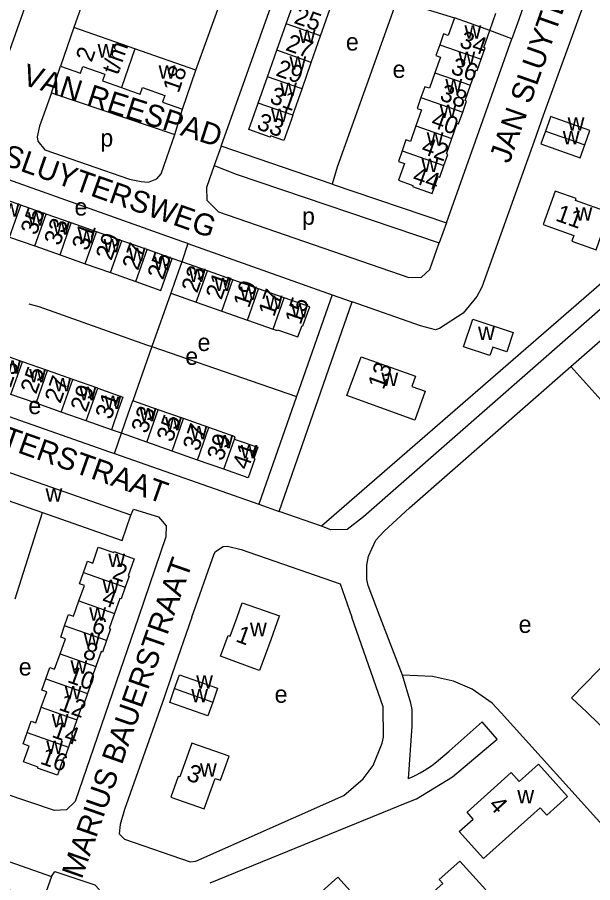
# Model space of a CAD drawing. Extents: x 162804 to 165059, y 381530 to 382901.
# Drawn here: x 163766.6 to 163898.9, y 381689 to 381888 of the extents above; entities that cross this region are included whole.
import ezdxf

# ---------------------------------------------------------------- set-up
doc = ezdxf.new("R2010")
doc.units = 0
for name, color, linetype in [('BLT_Basislijn', 7, 'Continuous'), ('BLT_Bebouwing', 7, 'Continuous'), ('BLT_Centroide', 7, 'Continuous'), ('BLT_Huisnummer', 7, 'Continuous'), ('BLT_Huisnummer_ tussenligend', 7, 'Continuous'), ('BLT_Huisnummer_reeks', 7, 'Continuous'), ('BLT_Onderverdeling_panden', 7, 'Continuous'), ('BLT_Straatnaam', 7, 'Continuous')]:
    doc.layers.add(name, color=color, linetype=linetype)

msp = doc.modelspace()

# ---------------------------------------------------------------- linework, layer by layer
at = {"layer": 'BLT_Basislijn'}
for p, q in [((163788.27, 381910.44), (163779.63, 381885.72)), ((163807.7, 381875.9), (163816.54, 381900.59)), ((163813.48, 381858.37), (163828.41, 381900.2)), ((163853.91, 381892.07), (163867.12, 381887.9)), ((163875.28, 381885.03), (163876.65, 381889)), ((163880.33, 381883.04), (163875.28, 381885.03)), ((163865.32, 381840.75), (163880.33, 381883.04)), ((163774.46, 381870.69), (163776.51, 381876.8)), ((163774.46, 381870.69), (163802.85, 381861.05)), ((163802.85, 381861.05), (163804.56, 381866.92)), ((163813.48, 381858.37), (163811.88, 381853.92)), ((163839.02, 381849.66), (163813.48, 381858.37)), ((163839.02, 381849.66), (163865.32, 381840.75)), ((163865.32, 381840.75), (163863.61, 381836.11)), ((163805.79, 381835.96), (163804.42, 381831.78)), ((163805.79, 381835.96), (163839.02, 381824.17)), ((163804.42, 381831.78), (163802.23, 381832.53)), ((163801.88, 381824.57), (163797.55, 381812.29)), ((163839.02, 381824.17), (163830.8, 381800.83)), ((163839.02, 381824.17), (163843.59, 381822.59)), ((163826.85, 381774.33), (163843.59, 381822.59)), ((163797.55, 381812.29), (163793.15, 381799.8)), ((163797.55, 381812.29), (163830.8, 381800.83)), ((163945.65, 381750), (163893.9, 381807.67)), ((163830.8, 381800.83), (163822.15, 381776.01)), ((163790.53, 381792.34), (163788.24, 381793.15)), ((163788.98, 381787.65), (163790.53, 381792.34)), ((163788.98, 381787.65), (163822.15, 381776.01)), ((163822.15, 381776.01), (163826.85, 381774.33)), ((163766.09, 381754.26), (163772.39, 381774.1)), ((163836.54, 381770.96), (163826.85, 381774.33)), ((163806.77, 381750), (163811.86, 381764.57)), ((163811.86, 381764.57), (163812.21, 381765.14)), ((163812.21, 381765.14), (163813.96, 381766.29)), ((163813.96, 381766.29), (163814.98, 381766.38)), ((163814.98, 381766.38), (163818.1, 381765.63)), ((163818.1, 381765.63), (163840.85, 381757.69)), ((163840.85, 381757.69), (163843.55, 381750)), ((163806.77, 381750), (163802.23, 381737.02)), ((163850.78, 381729.4), (163843.55, 381750)), ((163802.23, 381737.02), (163800.3, 381731.34)), ((163800.3, 381731.34), (163791.29, 381705.82)), ((163850.81, 381722.4), (163850.78, 381729.4)), ((163876.99, 381721.98), (163873.49, 381725.92)), ((163848.43, 381715.88), (163850.49, 381721.07)), ((163850.49, 381721.07), (163850.81, 381722.4)), ((163846.12, 381712.82), (163848.43, 381715.88)), ((163841.67, 381709.03), (163846.12, 381712.82)), ((163807.66, 381693.94), (163841.67, 381709.03)), ((163810.98, 381688.95), (163856.26, 381707.37)), ((163791.29, 381705.82), (163790.24, 381702.34)), ((163790.24, 381702.34), (163790.02, 381700.23)), ((163790.02, 381700.23), (163791.25, 381698.94)), ((163791.25, 381698.94), (163806.38, 381693.73)), ((163806.38, 381693.73), (163807.66, 381693.94))]:
    msp.add_line(p, q, dxfattribs=at)
for points in [[(163942.85, 382045.24), (163943.88, 382045.91), (163944.68, 382046.18), (163945.43, 382046.3), (163946.28, 382046.34), (163947.14, 382046.2), (163947.91, 382045.97), (163948.94, 382045.37), (163974.77, 382023.71), (164048.11, 381956.56), (164048.67, 381955.87), (164048.35, 381950.3), (163846.25, 381773.14), (163842.47, 381770.18), (163838.71, 381770.12), (163836.54, 381770.96)], [(163942.85, 382045.24), (163967.78, 382024.92), (164044.46, 381954.63), (164045.58, 381953.26), (163979.85, 381895.4), (163836.54, 381770.96)], [(163890.62, 381912.42), (163881.93, 381887.55), (163880.33, 381883.04)], [(163772.36, 381901.83), (163772.22, 381901.46), (163761.67, 381871.69)], [(163897.29, 381892.29), (163887.52, 381865.46), (163885.43, 381859.5), (163873.4, 381825.92), (163872.25, 381823.78), (163869.13, 381819.97), (163863.73, 381816.43), (163862.76, 381816.1), (163859.35, 381817.06), (163843.59, 381822.59)], [(163853.63, 381891.26), (163840.14, 381853.54), (163839.02, 381849.66)], [(163774.46, 381870.69), (163771.74, 381863.01), (163771.19, 381860.5), (163771.32, 381859.51), (163772.94, 381857.55), (163792.43, 381850.82), (163795.08, 381850.24), (163796.78, 381850.12), (163798.66, 381850.89), (163799.69, 381852.04), (163802.85, 381861.05)], [(163805.79, 381835.96), (163804.41, 381836.45), (163745.66, 381857.35)], [(163811.88, 381853.92), (163810.15, 381848.84), (163810.21, 381845.93), (163812.91, 381843.27), (163856.64, 381828.17), (163859.57, 381828.22), (163861.48, 381830), (163863.61, 381836.11)], [(163811.88, 381853.92), (163816.9, 381851.92), (163863.61, 381836.11)], [(163893.9, 381807.67), (163920.22, 381830.74)], [(163769.24, 381822.12), (163771.58, 381821.52), (163796.29, 381812.72), (163797.55, 381812.29)], [(163728.92, 381808.74), (163787.79, 381788.07), (163788.98, 381787.65)], [(163850.02, 381750), (163847.31, 381757.29), (163847.02, 381758.69), (163847.01, 381761.96), (163847.35, 381764.06), (163849.06, 381767.73), (163850.95, 381769.84), (163856.82, 381775.19), (163893.9, 381807.67)], [(163792.74, 381773.48), (163793.32, 381774.87), (163799.06, 381773.08), (163800.81, 381771.08), (163800.8, 381768.54), (163794.46, 381750)], [(163794.46, 381750), (163779.95, 381707.63), (163777.95, 381705.74), (163775.14, 381705.58), (163751.94, 381713.38)], [(163855.15, 381736.66), (163850.02, 381750)], [(163856.53, 381712.88), (163857.44, 381724.98), (163857.39, 381728.81), (163857.07, 381730.24), (163855.15, 381736.66)], [(163902.6, 381700.58), (163877.89, 381728.02), (163875.83, 381730.23), (163871.2, 381733.44), (163866.88, 381735.3), (163862.11, 381736.41), (163855.15, 381736.66)], [(163863.44, 381717.12), (163863.45, 381717.13), (163865.92, 381719.2), (163873.49, 381725.92)], [(163856.26, 381707.37), (163858.42, 381708.25), (163866.68, 381713.32), (163876.99, 381721.98)], [(163774.46, 381690.38), (163775.25, 381691.51), (163784.41, 381688.49), (163785.52, 381687.31)]]:
    msp.add_lwpolyline(points, dxfattribs=at)
msp.add_arc((163846.54, 381736.91), 26.02, 292.575, 310.4932, dxfattribs=at)
at = {"layer": 'BLT_Bebouwing'}
for p, q in [((163828.44, 381886.52), (163830.58, 381892.6)), ((163836.36, 381883.73), (163838.5, 381889.81)), ((163826.3, 381880.44), (163828.44, 381886.52)), ((163779.63, 381885.72), (163776.51, 381876.8)), ((163793.67, 381880.81), (163779.63, 381885.72)), ((163834.22, 381877.65), (163836.36, 381883.73)), ((163807.7, 381875.9), (163793.67, 381880.81)), ((163824.16, 381874.36), (163826.3, 381880.44)), ((163832.08, 381871.57), (163834.22, 381877.65)), ((163804.56, 381866.92), (163807.7, 381875.9)), ((163822.02, 381868.28), (163824.16, 381874.36)), ((163829.94, 381865.49), (163832.08, 381871.57)), ((163767.41, 381844.81), (163761.61, 381846.85)), ((163773.22, 381842.76), (163767.41, 381844.81)), ((163779.02, 381840.72), (163773.22, 381842.76)), ((163784.83, 381838.67), (163779.02, 381840.72)), ((163790.63, 381836.62), (163784.83, 381838.67)), ((163764.83, 381837.47), (163770.63, 381835.43)), ((163796.44, 381834.58), (163790.63, 381836.62)), ((163770.63, 381835.43), (163776.44, 381833.38)), ((163802.23, 381832.53), (163796.44, 381834.58)), ((163776.44, 381833.38), (163782.24, 381831.33)), ((163782.24, 381831.33), (163788.05, 381829.29)), ((163810.31, 381829.71), (163804.42, 381831.78)), ((163788.05, 381829.29), (163793.85, 381827.24)), ((163816.19, 381827.63), (163810.31, 381829.71)), ((163822.07, 381825.56), (163816.19, 381827.63)), ((163801.88, 381824.57), (163807.77, 381822.5)), ((163827.95, 381823.49), (163822.07, 381825.56)), ((163807.77, 381822.5), (163813.65, 381820.42)), ((163813.65, 381820.42), (163819.53, 381818.35)), ((163819.53, 381818.35), (163825.41, 381816.28)), ((163767.78, 381808.79), (163762.01, 381810.83)), ((163773.56, 381806.76), (163767.78, 381808.79)), ((163779.34, 381804.73), (163773.56, 381806.76)), ((163785.11, 381802.7), (163779.34, 381804.73)), ((163770.92, 381799.24), (163765.14, 381801.28)), ((163776.69, 381797.21), (163770.92, 381799.24)), ((163798.99, 381797.75), (163793.15, 381799.8)), ((163782.47, 381795.18), (163776.69, 381797.21)), ((163804.83, 381795.7), (163798.99, 381797.75)), ((163788.24, 381793.15), (163782.47, 381795.18)), ((163810.66, 381793.64), (163804.83, 381795.7)), ((163796.36, 381790.29), (163790.53, 381792.34)), ((163802.2, 381788.23), (163796.36, 381790.29)), ((163808.04, 381786.18), (163802.2, 381788.23)), ((163792.74, 381773.48), (163758.13, 381785.57)), ((163814.08, 381784.06), (163808.04, 381786.18)), ((163788.98, 381750.91), (163788.66, 381750)), ((163777.49, 381748.07), (163778.17, 381750)), ((163751.28, 381698.53), (163774.46, 381690.38))]:
    msp.add_line(p, q, dxfattribs=at)
for points in [[(163867.12, 381887.9), (163865.7, 381883.86), (163864.65, 381884.23), (163863.77, 381881.72)], [(163875.28, 381885.03), (163870.56, 381886.69), (163867.12, 381887.9)], [(163873.3, 381878.37), (163874.22, 381881), (163873.9, 381881.12), (163875.28, 381885.03)], [(163863.77, 381881.72), (163862.89, 381879.22), (163863.9, 381878.87), (163862.63, 381875.28)], [(163870.82, 381872.4), (163872.05, 381875.89), (163872.38, 381875.77), (163873.3, 381878.37)], [(163776.51, 381876.8), (163781.15, 381875.18), (163781.67, 381876.68), (163786.71, 381874.91), (163786.18, 381873.4), (163790.54, 381871.86)], [(163862.63, 381875.28), (163861.37, 381871.69), (163860.31, 381872.06), (163859.43, 381869.57)], [(163869.03, 381866.19), (163869.94, 381868.77), (163869.59, 381868.89), (163870.82, 381872.4)], [(163790.54, 381871.86), (163792.67, 381871.11), (163794.89, 381870.34), (163795.41, 381871.85), (163800.55, 381870.05), (163800.01, 381868.51), (163804.56, 381866.92)], [(163829.94, 381865.49), (163829.56, 381864.4), (163827.9, 381859.68), (163824.84, 381860.76), (163824.74, 381860.49), (163819.88, 381862.2), (163822.02, 381868.28)], [(163859.43, 381869.57), (163858.56, 381867.08), (163859.56, 381866.72), (163858.28, 381863.09)], [(163866.55, 381860.18), (163867.78, 381863.66), (163868.1, 381863.55), (163869.03, 381866.19)], [(163889.12, 381864.85), (163888.06, 381861.87)], [(163897.09, 381858.67), (163898.27, 381862), (163889.24, 381865.19), (163889.12, 381864.85)], [(163858.28, 381863.09), (163857, 381859.45), (163855.98, 381859.81), (163855.11, 381857.33)], [(163864.71, 381853.95), (163865.6, 381856.49), (163865.3, 381856.6), (163866.55, 381860.18)], [(163888.06, 381861.87), (163887.01, 381858.89), (163896.04, 381855.69), (163897.09, 381858.67)], [(163855.11, 381857.33), (163854.23, 381854.85), (163855.62, 381854.36), (163854.28, 381850.53), (163857.58, 381849.37), (163857.48, 381849.09), (163862.02, 381847.49), (163863.39, 381851.38), (163863.76, 381851.25), (163864.71, 381853.95)], [(163902.74, 381843.12), (163894.96, 381845.88), (163895.12, 381846.31), (163890.27, 381848.03), (163887.55, 381840.34), (163894.6, 381837.84), (163894.14, 381836.53), (163899.71, 381834.56), (163902.74, 381843.12)], [(163793.85, 381827.24), (163799.65, 381825.2), (163800.57, 381827.82), (163802.23, 381832.53)], [(163804.42, 381831.78), (163802.76, 381827.06), (163801.88, 381824.57)], [(163825.41, 381816.28), (163826.33, 381815.95), (163826.41, 381816.17), (163831.15, 381814.5), (163832.08, 381817.12), (163832.3, 381817.04), (163833.84, 381821.41), (163827.95, 381823.49)], [(163785.11, 381802.7), (163790.88, 381800.67), (163789.9, 381797.87), (163788.24, 381793.15)], [(163790.53, 381792.34), (163792.18, 381797.06), (163793.15, 381799.8)], [(163816.52, 381791.02), (163816.7, 381791.52), (163810.66, 381793.64)], [(163816.52, 381791.02), (163817.18, 381790.79), (163821.9, 381789.13), (163820.98, 381786.53), (163821.24, 381786.44), (163819.71, 381782.08), (163814.08, 381784.06)], [(163758.13, 381785.57), (163756.11, 381779.79), (163772.39, 381774.1)], [(163772.39, 381774.1), (163790.72, 381767.69), (163792.74, 381773.48)], [(163781.84, 381760.32), (163782.75, 381762.91), (163783.94, 381762.49), (163785.23, 381766.17), (163788.8, 381764.91), (163788.87, 381765.11), (163793.46, 381763.49), (163792.09, 381759.58), (163792.31, 381759.5), (163791.42, 381756.95)], [(163780.79, 381753.79), (163782.03, 381757.33), (163780.93, 381757.72), (163781.84, 381760.32)], [(163791.42, 381756.95), (163790.47, 381754.25), (163790.19, 381754.35), (163788.98, 381750.91)], [(163778.17, 381750), (163778.4, 381750.65), (163779.54, 381750.25), (163780.79, 381753.79)], [(163817.15, 381750), (163818.33, 381753.35), (163826.88, 381750.32), (163826.77, 381750)], [(163788.66, 381750), (163787.73, 381747.44), (163788.04, 381747.33), (163787.1, 381744.68)], [(163826.77, 381750), (163824.88, 381744.8), (163822.33, 381737.77), (163821.02, 381738.26), (163813.34, 381741.07), (163815.09, 381745.82), (163815.54, 381745.66), (163817.15, 381750)], [(163903.36, 381741), (163894.09, 381731.47), (163897.54, 381728.17), (163903.09, 381722.79), (163912.2, 381732.24), (163913.86, 381730.76), (163925.19, 381742.22), (163933.11, 381734.68), (163931.8, 381733.31), (163934.81, 381730.43), (163941.8, 381737.51), (163928.76, 381750)], [(163776.43, 381741.59), (163777.66, 381745.08), (163776.59, 381745.46), (163777.49, 381748.07)], [(163787.1, 381744.68), (163786.17, 381742.02), (163785.89, 381742.11), (163784.68, 381738.67)], [(163773.18, 381735.85), (163774.11, 381738.48), (163775.19, 381738.09), (163776.43, 381741.59)], [(163784.68, 381738.67), (163783.4, 381735.08), (163783.64, 381734.99), (163782.75, 381732.47)], [(163802.78, 381733.61), (163803.9, 381736.77), (163812.67, 381733.67), (163811.55, 381730.51)], [(163772.11, 381729.3), (163773.36, 381732.84), (163772.25, 381733.23), (163773.18, 381735.85)], [(163801.66, 381730.44), (163802.78, 381733.61)], [(163782.75, 381732.47), (163781.8, 381729.78), (163781.52, 381729.88), (163780.29, 381726.41)], [(163768.89, 381723.49), (163769.82, 381726.12), (163770.85, 381725.76), (163772.11, 381729.3)], [(163811.55, 381730.51), (163810.43, 381727.34), (163801.66, 381730.44)], [(163780.29, 381726.41), (163779.05, 381722.9), (163779.33, 381722.8), (163778.39, 381720.14)], [(163778.39, 381720.14), (163777.48, 381717.56), (163777.24, 381717.65), (163775.84, 381713.67), (163771.28, 381715.28), (163771.37, 381715.54), (163768.01, 381716.73), (163769.31, 381720.39), (163767.96, 381720.87), (163768.89, 381723.49)], [(163809.6, 381705.91), (163812.08, 381712.94), (163813.33, 381712.5), (163815.3, 381718.07), (163806.78, 381721.08), (163804.02, 381713.27), (163803.61, 381713.41), (163801.92, 381708.63), (163809.6, 381705.91)], [(163774.46, 381690.38), (163772.4, 381684.56), (163749.23, 381692.72)]]:
    msp.add_lwpolyline(points, dxfattribs=at)
for points in [[(163871.34, 381818.59), (163880.63, 381815.53), (163879.17, 381811.09), (163875.94, 381812.16), (163875.3, 381810.25), (163869.25, 381812.25)], [(163845.66, 381809.95), (163858.21, 381805.45), (163857.36, 381803.1), (163860.37, 381802.03), (163858, 381795.37), (163842.39, 381801)], [(163880.2, 381714.28), (163882.02, 381712.23), (163886.46, 381716.2), (163893.13, 381708.75), (163888.38, 381704.46), (163886.84, 381706.19), (163873.84, 381694.5), (163868.24, 381700.73), (163871.44, 381703.6), (163870.04, 381705.16)], [(163868.37, 381693.89), (163874.32, 381687.3), (163863.67, 381677.67), (163861.86, 381679.68), (163853.4, 381672.09), (163849.13, 381676.86), (163843.26, 381671.6), (163835.02, 381680.76), (163836.14, 381681.76), (163833.79, 381684.38), (163840.34, 381690.26), (163848.35, 381681.31), (163851.08, 381683.77), (163852.78, 381681.88), (163857.34, 381685.99), (163859.13, 381684), (163864.45, 381688.8), (163863.64, 381689.65)]]:
    msp.add_lwpolyline(points, close=True, dxfattribs=at)
at = {"layer": 'BLT_Onderverdeling_panden'}
for p, q in [((163836.36, 381883.73), (163828.44, 381886.52)), ((163793.67, 381880.81), (163790.54, 381871.86)), ((163834.22, 381877.65), (163826.3, 381880.44)), ((163863.77, 381881.72), (163873.3, 381878.37)), ((163832.08, 381871.57), (163824.16, 381874.36)), ((163862.63, 381875.28), (163870.82, 381872.4)), ((163829.94, 381865.49), (163822.02, 381868.28)), ((163859.43, 381869.57), (163869.03, 381866.19)), ((163858.28, 381863.09), (163866.55, 381860.18)), ((163888.06, 381861.87), (163897.09, 381858.67)), ((163855.11, 381857.33), (163864.71, 381853.95)), ((163764.83, 381837.47), (163767.41, 381844.81)), ((163770.63, 381835.43), (163773.22, 381842.76)), ((163776.44, 381833.38), (163779.02, 381840.72)), ((163782.24, 381831.33), (163784.83, 381838.67)), ((163788.05, 381829.29), (163790.63, 381836.62)), ((163793.85, 381827.24), (163796.44, 381834.58)), ((163807.77, 381822.5), (163810.31, 381829.71)), ((163813.65, 381820.42), (163816.19, 381827.63)), ((163819.53, 381818.35), (163822.07, 381825.56)), ((163825.41, 381816.28), (163827.95, 381823.49)), ((163765.14, 381801.28), (163767.78, 381808.79)), ((163770.92, 381799.24), (163773.56, 381806.76)), ((163776.69, 381797.21), (163779.34, 381804.73)), ((163782.47, 381795.18), (163785.11, 381802.7)), ((163796.36, 381790.29), (163798.99, 381797.75)), ((163802.2, 381788.23), (163804.83, 381795.7)), ((163808.04, 381786.18), (163810.66, 381793.64)), ((163814.08, 381784.06), (163816.52, 381791.02)), ((163781.84, 381760.32), (163791.42, 381756.95)), ((163780.79, 381753.79), (163788.98, 381750.91)), ((163787.1, 381744.68), (163777.49, 381748.07)), ((163776.43, 381741.59), (163784.68, 381738.67)), ((163773.18, 381735.85), (163782.75, 381732.47)), ((163802.78, 381733.61), (163811.55, 381730.51)), ((163772.11, 381729.3), (163780.29, 381726.41)), ((163768.89, 381723.49), (163778.39, 381720.14))]:
    msp.add_line(p, q, dxfattribs=at)

# ---------------------------------------------------------------- texts
at = {"layer": 'BLT_Centroide'}
for s, p in [('w', (163869.44, 381883.12)), ('w', (163831.33, 381882.09)), ('e', (163842.17, 381880.39)), ('w', (163785.08, 381878.78)), ('w', (163868.05, 381877.06)), ('w', (163829.19, 381876)), ('w', (163799.11, 381873.88)), ('e', (163852.9, 381874.08)), ('w', (163827.05, 381869.94)), ('w', (163865.04, 381870.75)), ('w', (163824.95, 381863.97)), ('w', (163863.73, 381864.88)), ('w', (163893.16, 381861.94)), ('p', (163785.7, 381858.29)), ('w', (163860.75, 381858.53)), ('w', (163892.05, 381858.78)), ('w', (163859.55, 381852.41)), ('w', (163763.22, 381842.16)), ('e', (163779.76, 381842.42)), ('w', (163894.99, 381841.28)), ('w', (163769.02, 381840.12)), ('p', (163832.08, 381840.3)), ('w', (163774.83, 381838.06)), ('w', (163780.62, 381836.03)), ('w', (163786.44, 381833.97)), ('w', (163792.23, 381831.94)), ('w', (163798.05, 381829.88)), ('w', (163806.09, 381827.14)), ('w', (163811.97, 381825.06)), ('w', (163817.86, 381822.98)), ('w', (163823.73, 381820.92)), ('w', (163829.62, 381818.97)), ('w', (163872.56, 381813.79)), ('e', (163808.06, 381811.26)), ('e', (163805.23, 381808.08)), ('w', (163763.58, 381806.05)), ('w', (163769.34, 381804.02)), ('w', (163850.33, 381803.19)), ('w', (163775.12, 381801.98)), ('w', (163780.91, 381799.95)), ('w', (163786.67, 381797.92)), ('e', (163769.14, 381796.75)), ('w', (163794.75, 381795.05)), ('w', (163800.59, 381793)), ('w', (163806.44, 381790.94)), ('w', (163812.38, 381788.84)), ('w', (163817.98, 381786.59)), ('w', (163773.1, 381776.62)), ('w', (163787.53, 381761.56)), ('w', (163786.19, 381755.62)), ('w', (163783.14, 381749.22)), ('w', (163820.11, 381745.66)), ('e', (163881.89, 381746.41)), ('w', (163781.85, 381743.38)), ('e', (163766.94, 381736.61)), ('w', (163778.84, 381737.03)), ('w', (163807.73, 381733.62)), ('w', (163777.51, 381731.12)), ('w', (163806.6, 381730.47)), ('e', (163825.78, 381730.34)), ('w', (163774.52, 381724.72)), ('w', (163773.26, 381718.59)), ('w', (163808.61, 381713.34)), ('w', (163881.59, 381707.18))]:
    msp.add_text(s, height=4, dxfattribs=at).set_placement(p)
at = {"layer": 'BLT_Huisnummer'}
for s, rotation, p in [('27', 340.6076, (163828.09, 381880.53)), ('34', 340.6259, (163868.05, 381881.29)), ('38', 340.6292, (163863.51, 381869.05)), ('33', 340.6019, (163821.43, 381862.38)), ('44', 340.6307, (163857.25, 381850.12)), ('35', 70.5841, (163770.98, 381837.72)), ('11', 340.5332, (163890.17, 381841.32)), ('31', 70.5816, (163782.76, 381834.14)), ('27', 70.5829, (163794.34, 381829.62)), ('23', 70.5837, (163807.95, 381824.4)), ('19', 70.5862, (163819.86, 381820.97)), ('15', 70.5874, (163831.75, 381817.12)), ('13', 70.0282, (163850.83, 381802.2)), ('25', 70.6229, (163770.93, 381801.16)), ('29', 70.6214, (163782.43, 381796.99)), ('33', 70.6214, (163796.41, 381792.09)), ('37', 70.6147, (163808.26, 381788.02)), ('41', 70.6211, (163819.67, 381783.72)), ('2', 340.6298, (163788.21, 381759.01)), ('6', 340.5444, (163783.41, 381746.72)), ('1', 339.8797, (163816.61, 381744.52)), ('10', 340.5384, (163777.9, 381735.15)), ('16', 340.5501, (163771.65, 381716.4)), ('3', 340.5194, (163805.28, 381712.62)), ('4', 312.2211, (163874.77, 381706.68))]:
    msp.add_text(s, height=4, rotation=rotation, dxfattribs=at).set_placement(p)
at = {"layer": 'BLT_Huisnummer_ tussenligend'}
for s, rotation, p in [('25', 340.6076, (163830.01, 381886.76)), ('29', 340.6076, (163825.84, 381874.68)), ('36', 340.6259, (163866.06, 381875.18)), ('31', 340.6076, (163824.42, 381868.42)), ('40', 340.6292, (163861.52, 381862.93)), ('42', 340.6292, (163859.27, 381856.82)), ('33', 70.5816, (163776.37, 381835.31)), ('29', 70.5829, (163788.24, 381831.89)), ('25', 70.5837, (163800.12, 381827.46)), ('21', 70.5862, (163813.54, 381822.85)), ('17', 70.5874, (163825.64, 381818.96)), ('23', 70.621, (163765.04, 381802.65)), ('27', 70.6229, (163776.51, 381799.02)), ('31', 70.6214, (163788.15, 381795.3)), ('35', 70.6214, (163802.25, 381790.1)), ('39', 70.6147, (163813.84, 381785.77)), ('4', 340.6298, (163785.8, 381753.03)), ('8', 340.5444, (163781.43, 381740.74)), ('12', 340.5384, (163775.92, 381728.77)), ('14', 340.5384, (163774.31, 381722.53))]:
    msp.add_text(s, height=4, rotation=rotation, dxfattribs=at).set_placement(p)
at = {"layer": 'BLT_Huisnummer_reeks'}
for s, rotation, p in [('t/m', 70.7276, (163789.73, 381874.59)), ('2', 70.7208, (163783.69, 381877.52)), ('18', 70.7273, (163803.69, 381870.44))]:
    msp.add_text(s, height=4, rotation=rotation, dxfattribs=at).set_placement(p)
at = {"layer": 'BLT_Straatnaam'}
for s, height, rotation, p in [('JAN SLUYTERSWEG', 5, 70.5997, (163879.76, 381854.2)), ('VAN REESPAD', 4.9999, 342.1858, (163767.43, 381872.68)), ('JAN SLUYTERSWEG', 5, 340.564, (163749.21, 381859.07)), ("D'HONDECOETERSTRAAT", 5, 340.5203, (163720.42, 381804.26)), ('MARIUS BAUERSTRAAT', 5, 70.6941, (163781.42, 381689.61))]:
    msp.add_text(s, height=height, rotation=rotation, dxfattribs=at).set_placement(p)

doc.saveas('drawing.dxf')
